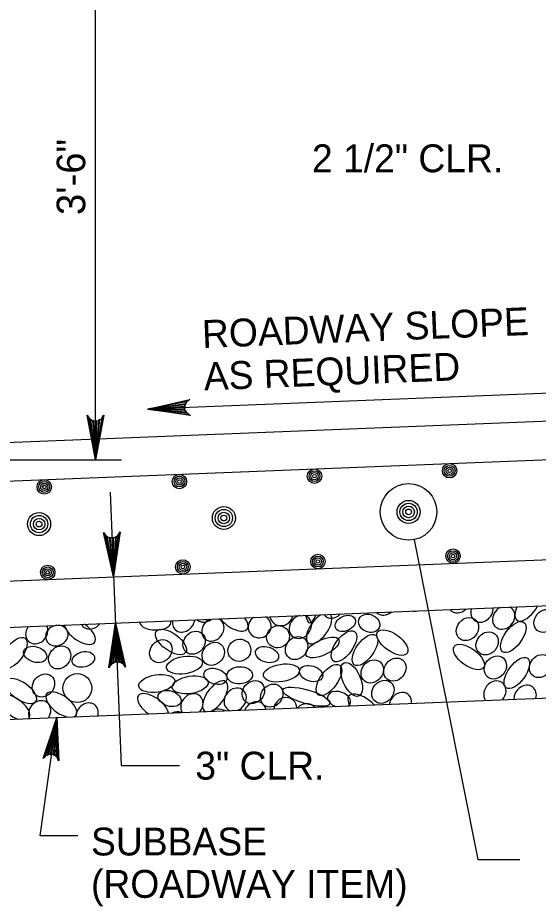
# Model space of a CAD drawing. Extents: x 638167 to 640248, y 296544 to 298920.
# Drawn here: x 639646.3 to 639703.7, y 298723.4 to 298821.3 of the extents above; entities that cross this region are included whole.
import ezdxf

# ---------------------------------------------------------------- set-up
doc = ezdxf.new("R2010")
doc.units = 0
doc.layers.add('1', color=7, linetype='Continuous')
doc.layers.add('50', color=7, linetype='Continuous')

# ---------------------------------------------------------------- blocks, each defined once
blk = doc.blocks.new('BAR')
at = {"layer": '50'}
for radius in [2, 1.5, 1, 0.5]:
    blk.add_circle((0, 0), radius, dxfattribs=at)

msp = doc.modelspace()

# ---------------------------------------------------------------- linework, layer by layer
at = {"layer": '1'}
for p, q in [((639654.898, 298772.596), (639654.898, 298843.716)), ((639792.111, 298780.369), (639597.766, 298772.596)), ((639706.247, 298780.021), (639660.639, 298778.197)), ((639569.769, 298767.239), (639757.112, 298774.733)), ((639599.028, 298772.596), (639657.756, 298772.596)), ((639656.525, 298769.037), (639657.731, 298738.906)), ((639565.771, 298756.064), (639757.552, 298763.735)), ((639690.046, 298763.811), (639697.08, 298728.549)), ((639599.034, 298752.31), (639792.923, 298760.066)), ((639599.034, 298742.142), (639793.329, 298749.914)), ((639648.784, 298731.167), (639650.65, 298744.207)), ((639657.731, 298738.906), (639664.184, 298738.906)), ((639652.963, 298731.167), (639648.784, 298731.167)), ((639697.08, 298728.549), (639701.701, 298728.549))]:
    msp.add_line(p, q, dxfattribs=at)
for points in [[(639660.639, 298778.197), (639665.298, 298779.265), (639665.122, 298779.132), (639664.946, 298779), (639664.86, 298778.839), (639664.773, 298778.677), (639664.752, 298778.519), (639664.731, 298778.36), (639664.764, 298778.204), (639664.798, 298778.048), (639664.897, 298777.894), (639664.997, 298777.741), (639665.183, 298777.623), (639665.369, 298777.504), (639660.639, 298778.197), (639665.183, 298777.623), (639664.997, 298777.741), (639660.639, 298778.197), (639664.897, 298777.894), (639664.798, 298778.048), (639660.639, 298778.197), (639664.764, 298778.204), (639664.731, 298778.36), (639660.639, 298778.197), (639664.752, 298778.519), (639664.773, 298778.677), (639660.639, 298778.197), (639664.86, 298778.839), (639664.946, 298779), (639660.639, 298778.197), (639665.122, 298779.132)], [(639654.898, 298772.596), (639653.973, 298777.528), (639654.105, 298777.338), (639654.237, 298777.148), (639654.402, 298777.05), (639654.567, 298776.952), (639654.733, 298776.924), (639654.898, 298776.895), (639655.063, 298776.924), (639655.229, 298776.952), (639655.394, 298777.05), (639655.56, 298777.148), (639655.691, 298777.338), (639655.823, 298777.528), (639654.898, 298772.596), (639655.691, 298777.338), (639655.56, 298777.148), (639654.898, 298772.596), (639655.394, 298777.05), (639655.229, 298776.952), (639654.898, 298772.596), (639655.063, 298776.924), (639654.898, 298776.895), (639654.898, 298772.596), (639654.733, 298776.924), (639654.567, 298776.952), (639654.898, 298772.596), (639654.402, 298777.05), (639654.237, 298777.148), (639654.898, 298772.596), (639654.105, 298777.338)], [(639656.898, 298759.709), (639655.777, 298764.6), (639655.916, 298764.416), (639656.055, 298764.231), (639656.225, 298764.14), (639656.394, 298764.048), (639656.56, 298764.027), (639656.727, 298764.005), (639656.891, 298764.04), (639657.055, 298764.075), (639657.216, 298764.179), (639657.377, 298764.284), (639657.501, 298764.479), (639657.625, 298764.674), (639656.898, 298759.709), (639657.501, 298764.479), (639657.377, 298764.284), (639656.898, 298759.709), (639657.216, 298764.179), (639657.055, 298764.075), (639656.898, 298759.709), (639656.891, 298764.04), (639656.727, 298764.005), (639656.898, 298759.709), (639656.56, 298764.027), (639656.394, 298764.048), (639656.898, 298759.709), (639656.225, 298764.14), (639656.055, 298764.231), (639656.898, 298759.709), (639655.916, 298764.416)], [(639657.101, 298754.633), (639658.223, 298749.741), (639658.084, 298749.926), (639657.944, 298750.11), (639657.775, 298750.202), (639657.606, 298750.293), (639657.44, 298750.315), (639657.273, 298750.336), (639657.109, 298750.301), (639656.945, 298750.266), (639656.784, 298750.162), (639656.622, 298750.057), (639656.498, 298749.862), (639656.375, 298749.667), (639657.101, 298754.633), (639656.498, 298749.862), (639656.622, 298750.057), (639657.101, 298754.633), (639656.784, 298750.162), (639656.945, 298750.266), (639657.101, 298754.633), (639657.109, 298750.301), (639657.273, 298750.336), (639657.101, 298754.633), (639657.44, 298750.315), (639657.606, 298750.293), (639657.101, 298754.633), (639657.775, 298750.202), (639657.944, 298750.11), (639657.101, 298754.633), (639658.084, 298749.926)], [(639650.65, 298744.207), (639650.857, 298739.431), (639650.758, 298739.628), (639650.66, 298739.825), (639650.517, 298739.94), (639650.374, 298740.055), (639650.222, 298740.104), (639650.07, 298740.153), (639649.91, 298740.148), (639649.751, 298740.144), (639649.581, 298740.074), (639649.412, 298740.004), (639649.263, 298739.842), (639649.113, 298739.681), (639650.65, 298744.207), (639649.263, 298739.842), (639649.412, 298740.004), (639650.65, 298744.207), (639649.581, 298740.074), (639649.751, 298740.144), (639650.65, 298744.207), (639649.91, 298740.148), (639650.07, 298740.153), (639650.65, 298744.207), (639650.222, 298740.104), (639650.374, 298740.055), (639650.65, 298744.207), (639650.517, 298739.94), (639650.66, 298739.825), (639650.65, 298744.207), (639650.758, 298739.628)]]:
    msp.add_lwpolyline(points, dxfattribs=at)
for centre, radius in [((639689.435, 298766.87), 3.119), ((639652.899, 298747.456), 1.595)]:
    msp.add_circle(centre, radius, dxfattribs=at)
for centre, major_axis, ratio, start_param, end_param in [((639695.002, 298757.016), (0.86, 1.048), 0.844245, 2.967408, 4.603431), ((639697.522, 298755.99), (0.86, 1.048), 0.844245, 2.008108, 5.562731), ((639699.927, 298755.215), (0.86, 1.048), 0.844245, 1.11244, 6.458399), ((639702.557, 298756.549), (-1.174, -1.624), 0.479042, 5.130486, 8.155839), ((639670.016, 298755.136), (-1.624, 1.174), 0.479042, 1.014341, 4.173787), ((639673.004, 298754.223), (-1.167, -0.522), 0.948581, 4.858014, 10.05193), ((639675.398, 298755.556), (-1.167, -0.522), 0.948581, 6.041055, 8.868889), ((639677.491, 298754.198), (0.86, 1.048), 0.844245, 0.812597, 6.758242), ((639679.563, 298754.038), (-1.174, -1.624), 0.479042, 3.984367, 9.301958), ((639678.823, 298757.332), (0.301, 2.685), 0.282192, 2.36721, 4.002176), ((639681.119, 298756.432), (0.86, 1.048), 0.844245, 2.937326, 4.633513), ((639686.855, 298756.756), (0.86, 1.048), 0.844245, 3.041618, 4.529221), ((639688.118, 298757.546), (-1.174, -1.624), 0.479042, 0.238343, 0.481611), ((639690.298, 298757.213), (0.86, 1.048), 0.844245, 3.627473, 3.943366), ((639648.432, 298753.604), (0.86, 1.048), 0.844245, 1.646659, 5.92418), ((639650.638, 298753.246), (-1.155, -0.516), 0.87402, 4.347672, 10.501851), ((639653.178, 298753.681), (-1.624, 1.174), 0.479042, 0.443803, 4.744324), ((639654.459, 298755.226), (0.86, 1.048), 0.844245, 2.798262, 4.772577), ((639661.511, 298754.723), (1.717, -0.002), 0.504072, 3.123827, 6.463685), ((639664.614, 298754.898), (0.86, 1.048), 0.844245, 2.187172, 5.383667), ((639667.029, 298755.995), (0.86, 1.048), 0.844245, 3.07937, 4.491469), ((639667.85, 298753.904), (0.86, 1.048), 0.844245, 1.061779, 6.50906), ((639698.95, 298746.966), (0.86, 1.048), 0.844245, 4.644979, 9.209045), ((639668.101, 298746.536), (-1.174, -1.624), 0.479042, 0.613344, 6.389796), ((639670.31, 298746.179), (0.86, 1.048), 0.844245, 4.147339, 9.706685), ((639702.291, 298746.495), (0.86, 1.048), 0.844245, 5.179508, 8.674516), ((639645.954, 298745.33), (-1.624, 1.174), 0.479042, 3.037298, 8.434015), ((639651.133, 298745.621), (-1.624, 1.174), 0.479042, 2.873239, 8.598074), ((639661.247, 298745.441), (-1.624, 1.174), 0.479042, 3.57213, 7.899183), ((639665.532, 298745.555), (0.86, 1.048), 0.844245, 4.720434, 9.133591), ((639675.854, 298745.183), (-1.167, -0.522), 0.948581, 2.768835, 5.857924), ((639681.758, 298746.195), (1.251, -0.386), 0.646802, 5.825434, 10.881517), ((639684.44, 298745.384), (-1.624, 1.174), 0.479042, 4.285286, 7.186027), ((639688.538, 298745.691), (0.86, 1.048), 0.844245, 5.380866, 8.473158), ((639648.735, 298744.783), (0.86, 1.048), 0.844245, 4.815265, 9.038759), ((639653.976, 298744.537), (0.86, 1.048), 0.844245, 5.200099, 8.653925), ((639672.477, 298744.681), (0.86, 1.048), 0.844245, 5.676034, 8.17799), ((639678.138, 298744.498), (-1.167, -0.522), 0.948581, 3.464469, 5.16229), ((639663.715, 298743.562), (0.86, 1.048), 0.844245, 0.243434, 1.04422), ((639670.311, 298743.74), (2.42, -1.201), 0.282192, 2.12602, 3.204967)]:
    msp.add_ellipse(centre, major_axis=major_axis, ratio=ratio, start_param=start_param, end_param=end_param, dxfattribs=at)
for centre, major_axis, ratio in [((639704.493, 298754.857), (0.86, 1.048), 0.844245), ((639682.459, 298754.581), (1.058, 0.529), 0.687276), ((639685.092, 298754.594), (1.096, -0.509), 0.796199), ((639695.925, 298753.957), (0.86, 1.048), 0.844245), ((639675.033, 298753.11), (-1.167, -0.522), 0.948581), ((639700.979, 298753.076), (-1.174, -1.624), 0.479042), ((639645.951, 298751.325), (-1.174, -1.624), 0.479042), ((639663.217, 298752.542), (-1.624, 1.174), 0.479042), ((639665.781, 298752.449), (0.86, 1.048), 0.844245), ((639677.081, 298751.861), (0.86, 1.048), 0.844245), ((639682.3, 298752.063), (-1.174, -1.624), 0.479042), ((639684.616, 298751.649), (-1.174, -1.624), 0.479042), ((639687.645, 298752.467), (-1.624, 1.174), 0.479042), ((639698.097, 298752.376), (0.86, 1.048), 0.844245), ((639650.947, 298750.836), (0.86, 1.048), 0.844245), ((639662.108, 298751.522), (0.86, 1.048), 0.844245), ((639667.893, 298751.222), (0.86, 1.048), 0.844245), ((639670.771, 298751.621), (-1.167, -0.522), 0.948581), ((639679.954, 298751.937), (1.803, 0.852), 0.422273), ((639696.085, 298750.877), (-1.624, 1.174), 0.479042), ((639648.251, 298751.16), (1.251, -0.386), 0.646802), ((639653.57, 298750.617), (1.224, 0.296), 0.666084), ((639673.818, 298751.142), (1.251, -0.386), 0.646802), ((639703.985, 298749.879), (0.86, 1.048), 0.844245), ((639664.712, 298749.986), (-1.979, -0.318), 0.479042), ((639680.648, 298748.347), (-1.174, -1.624), 0.479042), ((639683.148, 298748.411), (0.82, -1.829), 0.479042), ((639685.429, 298749.287), (0.86, 1.048), 0.844245), ((639687.921, 298749.488), (0.86, 1.048), 0.844245), ((639699.003, 298749.726), (0.86, 1.048), 0.844245), ((639701.37, 298749.117), (-1.174, -1.624), 0.479042), ((639668.126, 298748.746), (1.251, -0.386), 0.646802), ((639670.812, 298748.865), (1.409, 0.056), 0.671766), ((639675.405, 298749.118), (-1.979, -0.318), 0.479042), ((639678.691, 298749.048), (1.251, -0.386), 0.646802), ((639646.675, 298747.132), (-1.624, 1.174), 0.479042), ((639649.159, 298747.739), (0.86, 1.048), 0.844245), ((639661.655, 298747.957), (-1.979, -0.318), 0.479042), ((639665.35, 298747.807), (-1.979, -0.318), 0.479042), ((639672.309, 298747.003), (0.86, 1.048), 0.844245), ((639686.597, 298747.044), (0.86, 1.048), 0.844245), ((639674.34, 298746.626), (0.86, 1.048), 0.844245), ((639678.163, 298746.501), (2.592, -0.763), 0.282192), ((639663.074, 298746.301), (1.251, -0.386), 0.646802)]:
    msp.add_ellipse(centre, major_axis=major_axis, ratio=ratio, dxfattribs=at)

# ---------------------------------------------------------------- block references
at = {"layer": '1', "xscale": 0.39687579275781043, "yscale": 0.3968757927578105, "rotation": -82.05765865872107}
for p in [(639693.958, 298771.412), (639664.156, 298770.22), (639679.057, 298770.816), (639649.254, 298769.624), (639679.433, 298761.404), (639694.335, 298762), (639649.631, 298760.212), (639664.532, 298760.808)]:
    msp.add_blockref('BAR', p, dxfattribs=at)
at = {"layer": '1', "xscale": 0.6349782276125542, "yscale": 0.6349782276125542}
for p in [(639689.435, 298766.87), (639669.058, 298766.2), (639648.681, 298765.53)]:
    msp.add_blockref('BAR', p, dxfattribs=at)

# ---------------------------------------------------------------- texts
at = {"layer": '1'}
for s, height, rotation, p in [('3\'-6"', 3.15, 90, (639653.77, 298799.6)), ('ROADWAY SLOPE', 3.072, 2.29061, (639666.709, 298784.935)), ('AS REQUIRED', 3.072, 2.29061, (639666.896, 298780.266)), ('3" CLR.', 3.072, 360, (639665.906, 298737.366)), ('SUBBASE', 3.072, 360, (639654.409, 298729)), ('(ROADWAY ITEM)', 3.072, 360, (639654.409, 298724.328))]:
    msp.add_text(s, height=height, rotation=rotation, dxfattribs=at).set_placement(p)
msp.add_text('2 1/2" CLR.', height=3.072, dxfattribs=at).set_placement((639678.779, 298804.319))

doc.saveas('drawing.dxf')
